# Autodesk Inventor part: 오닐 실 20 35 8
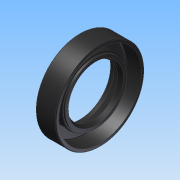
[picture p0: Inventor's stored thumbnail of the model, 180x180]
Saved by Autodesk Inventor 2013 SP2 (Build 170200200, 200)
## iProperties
Created: 2025-09
Part Number: 오닐 실 20 35 8
Material: Generic
Document SubType Name: Modeling
Designer: a
Density: 1 g/cm^3
Author: a
변환 표준: STEP AP214IS
전처리기: Build: 200, Release: 2013 SP2 Update 6 - Date: Thu 07/17/2014
전송 단위: 밀리미터
불확실성: 0.01
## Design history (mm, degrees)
node "오일 실 20 35 81"
body "Solid1"
node "기준1"
